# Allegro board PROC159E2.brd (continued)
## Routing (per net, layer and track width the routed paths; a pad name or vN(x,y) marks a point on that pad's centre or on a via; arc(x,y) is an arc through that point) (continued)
HSEC_MMC0_D1: length 104.8
  L08_SIG2 w0.091: v1(49.11,52.98) 49.6,52.49 51.45,52.49 53.6,54.63 65.11,54.63 66.27,53.47 67.27,53.47 68.03,52.71 70.05,52.71 71.08,51.68 75.63,51.68 78.21,49.1 78.21,40.54 79.82,38.93 79.82,33.07 80.78,32.1 80.78,30.79 83.76,27.82 83.76,26.1 83.9,25.97 84.23,25.97 84.36,25.84 84.36,25.65 84.23,25.51 83.9,25.51 83.76,25.38 83.76,25.19 83.9,25.06 84.23,25.06 84.36,24.92 84.36,24.73 84.23,24.6 83.9,24.6 83.76,24.47 83.76,24.28 83.9,24.14 84.23,24.14 84.36,24.01 84.36,23.82 84.23,23.68 83.9,23.68 83.76,23.55 83.76,23.36 83.9,23.23 84.23,23.23 84.36,23.09 84.36,22.9 84.23,22.77 83.9,22.77 83.76,22.64 83.76,22.45 83.9,22.31 84.23,22.31 84.36,22.18 84.36,21.99 84.23,21.86 83.9,21.86 83.76,21.72 83.76,21.53 83.9,21.4 84.23,21.4 84.36,21.26 84.36,21.08 84.23,20.94 83.9,20.94 83.76,20.81 83.76,20.41 87.89,16.29 88.24,16.29 88.37,16.42 88.37,16.79 88.51,16.92 88.69,16.92 88.83,16.79 88.83,16.42 88.96,16.29 89.15,16.29 89.29,16.42 89.29,16.79 89.42,16.92 89.61,16.92 89.74,16.79 89.74,16.42 89.88,16.29 92.4,16.29 100.05,8.64 101.41,8.64 104,6.05 106.76,6.05 v1(107.24,5.58)
  BOTTOM w0.147: RA3.2 49.35,52.69 49.11,52.94 v1(49.11,52.98) ; J15.166 106.44,4.78 v1(107.24,5.58)
HSEC_MMC0_D2: length 104.7
  TOP w0.147: J15.167 v1(107.24,4.56)
  L08_SIG2 w0.091: v1(107.24,4.56) 107.69,5.01 107.69,7.8 107.29,8.19 103.48,8.19 100.84,10.83 99.96,10.83 99.42,11.37 99.42,11.92 97.88,13.47 96.95,13.47 93.09,17.33 93.09,19.05 92.23,19.92 91.42,19.92 90.42,20.93 90.42,21.12 90.7,21.4 90.7,21.59 90.57,21.72 90.38,21.72 90.09,21.44 89.9,21.44 89.77,21.58 89.77,21.77 90.05,22.05 90.05,22.24 89.92,22.37 89.73,22.37 89.45,22.09 89.26,22.09 89.12,22.22 89.12,22.41 89.41,22.69 89.41,22.88 89.27,23.02 89.08,23.02 88.8,22.73 88.61,22.73 88.48,22.87 88.48,23.06 88.76,23.34 88.76,23.53 88.63,23.66 88.44,23.66 88.15,23.38 87.96,23.38 87.83,23.52 87.83,23.7 88.11,23.99 88.11,24.18 87.98,24.31 87.79,24.31 87.51,24.03 87.23,24.03 87.02,24.24 87.02,26.26 83.12,30.16 83.12,40.12 81.4,41.83 81.4,44.69 79.31,46.78 79.31,50.72 77.34,52.69 71.51,52.69 70.72,53.48 68.35,53.48 67.59,54.24 66.59,54.24 65.43,55.41 50.49,55.41 48.89,53.81 48.45,53.81 48.22,53.58 v1(48.22,52.98)
  BOTTOM w0.147: v1(48.22,52.98) 48.22,52.6 RA3.1
HSEC_MMC0_D3: length 104.7
  L08_SIG2 w0.091: v1(107.24,7.61) 106.93,7.92 103.36,7.92 101.77,9.51 100.34,9.51 99.15,10.71 99.15,11.77 97.73,13.19 96.84,13.19 92.82,17.21 92.82,18.84 92.18,19.48 90.07,19.48 89.71,19.84 89.71,20.03 89.94,20.27 89.94,20.46 89.81,20.59 89.62,20.59 89.38,20.35 89.19,20.35 89.06,20.49 89.06,20.68 89.3,20.91 89.3,21.1 89.16,21.24 88.97,21.24 88.74,21 88.55,21 88.41,21.13 88.41,21.32 88.65,21.56 88.65,21.75 88.52,21.88 88.33,21.88 88.09,21.65 87.9,21.65 87.77,21.78 87.77,21.97 88,22.21 88,22.4 87.87,22.53 87.68,22.53 87.44,22.29 87.25,22.29 86.56,22.98 86.56,26.31 82.67,30.2 82.67,40 81.09,41.59 81.09,44.5 79.03,46.55 79.03,50.61 77.22,52.42 71.4,52.42 70.53,53.29 68.27,53.29 67.51,54.05 66.51,54.05 65.35,55.21 50.74,55.21 48.68,53.15 48.68,52.84 48.4,52.55 47.76,52.55 v1(47.33,52.98)
  BOTTOM w0.147: v1(47.33,52.98) 47.33,52.5 RA5.4 ; J15.168 107.24,3.92 107.73,4.41 107.73,7.11 v1(107.24,7.61)
HSEC_MMC0_SDCD: length 102.5
  L08_SIG2 w0.091: v1(108.84,6.59) 108.32,7.11 108.32,8.1 107.54,8.88 105.38,8.88 104.79,9.48 103.37,9.48 100.73,12.11 100.07,12.11 98.47,13.7 98.47,13.89 97.6,14.76 96.44,14.76 93.74,17.46 93.74,20.5 84.58,29.66 84.58,31.93 83.93,32.59 83.93,40.38 82.01,42.29 82.01,45.02 79.86,47.17 79.86,50.95 77.56,53.24 71.6,53.24 70.97,53.87 68.56,53.87 67.8,54.63 66.75,54.63 65.59,55.79 48.37,55.79 v1(45.55,52.98)
  BOTTOM w0.147: J15.170 108.04,5.79 v1(108.84,6.59) ; v1(45.55,52.98) 45.55,52.94 45.8,52.69 RA5.2
HSEC_MMC0_WP: length 104.3
  TOP w0.147: v1(108.84,7.61) 108.04,6.81 J15.169
  L08_SIG2 w0.091: v1(108.84,7.61) 108.84,8.06 107.69,9.21 105.49,9.21 104.95,9.75 103.48,9.75 101.87,11.36 101.87,11.71 100.07,13.52 99.23,13.52 97.71,15.04 96.55,15.04 94.02,17.57 94.02,20.72 84.98,29.76 84.98,32.02 84.31,32.68 84.31,40.47 82.28,42.5 82.28,45.13 80.13,47.28 80.13,51.06 77.68,53.52 71.6,53.52 70.98,54.14 68.61,54.14 67.98,54.76 67.98,55.26 67.71,55.53 67.18,55.53 66.39,56.33 65.89,56.33 65.55,55.99 47.77,55.99 v1(45.59,53.8)
  BOTTOM w0.147: RA5.1 45.16,52.63 44.98,52.81 44.98,53.2 v1(45.59,53.8)
HSEC_SDFM0_CLK0: length 64.2
  TOP w0.147: U1.B16 v1(65.78,46.43)
  L08_SIG2 w0.091: v1(65.78,46.43) 65.37,46.02 64.02,46.02 63.79,45.79 63.79,42.27 64.04,42.02 67.69,42.02 68.67,41.04 69.34,41.04 70.13,40.25 70.13,34.22 69.45,33.54 69.45,27.41 67.64,25.6 67.64,23.36 66.6,22.32 66.6,18.71 65.82,17.92 62.81,17.92 59.35,14.46 59.35,13.26 56.97,10.87 55.19,10.87 49.89,5.58 v1(48.64,5.58)
  BOTTOM w0.147: J15.72 48.64,3.92 48.18,4.37 48.18,5.12 v1(48.64,5.58)
HSEC_SDFM0_CLK1: length 59.5
  TOP w0.147: R422.2 63.82,49.19 v1(65.78,47.23) U1.A16 ; v1(61.44,6.59) 60.64,5.79 J15.101
  L08_SIG2 w0.091: v1(65.78,47.23) 66.15,47.23 66.64,46.75 66.64,45.38 71.15,40.87 71.15,39.29 71.8,38.64 71.8,34.8 70.22,33.22 70.22,29.96 71.35,28.83 71.35,27.58 70.93,27.16 70.93,23.96 69.56,22.6 69.56,18.72 66.84,16 65.11,16 59.85,10.75 59.85,8.18 v1(61.44,6.59)
HSEC_SDFM0_CLK2: length 63.4
  TOP w0.147: U1.B15 v1(64.98,46.43) ; J15.105 62.24,5.71 v1(63.03,6.5)
  L08_SIG2 w0.091: v1(64.98,46.43) 65.23,46.43 65.62,46.82 65.97,46.82 66.36,46.43 66.36,45.3 70.86,40.8 70.86,34.13 70.03,33.3 70.03,26.95 68.37,25.3 68.37,23.75 69.31,22.81 69.31,18.75 67.23,16.66 63.79,16.66 58.56,11.43 58.56,7.49 59.14,6.91 59.14,6.53 59.64,6.04 59.98,6.04 60.63,5.38 60.63,4.76 61.26,4.13 61.62,4.13 62.61,5.12 62.61,6.07 v1(63.03,6.5)
HSEC_SDFM0_CLK3: length 57.5
  TOP w0.147: v1(63.72,10.39) 63.72,9.94 63.88,9.77 63.88,4.44 63.84,4.4 J15.109 ; U1.A15 v1(64.98,47.23)
  L08_SIG2 w0.091: v1(64.98,47.23) 64.98,47.6 65.2,47.82 67.38,47.82 68.1,47.1 68.1,44.61 71.64,41.07 71.64,39.5 72.25,38.89 72.25,34.65 71.5,33.91 71.5,32.87 71.25,32.62 71.25,32.04 71.97,31.31 71.97,26.93 73.43,25.47 73.43,23.78 72.25,22.6 72.25,18.8 71.5,18.05 69.43,18.05 63.98,12.6 63.98,10.65 v1(63.72,10.39)
HSEC_SDFM0_D0: length 53.6
  TOP w0.147: J15.91 v1(56.64,4.56) ; U1.D14 v1(64.18,44.83)
  L08_SIG2 w0.091: v1(56.64,4.56) 57.73,5.65 57.73,11.12 63.63,17.02 65.77,17.02 66.08,17.33 66.08,17.88 66.82,18.62 66.82,22.23 67.89,23.29 67.89,25.5 69.64,27.26 69.64,33.46 70.37,34.19 70.37,40.6 66.54,44.42 64.59,44.42 v1(64.18,44.83)
HSEC_SDFM0_D1: length 85.7
  TOP w0.147: J15.99 v1(59.84,4.56) ; U1.D13 v1(63.38,44.83)
  L08_SIG2 w0.091: v1(59.84,4.56) 60.81,3.58 62.93,3.58 63.65,4.31 63.65,6.72 66.72,9.78 66.93,10 66.93,12.29 69.22,14.58 74.45,14.58 78.59,18.71 78.59,20.28 79.04,20.72 79.04,24.92 80.95,26.83 80.95,28.49 78.21,31.23 78.21,37.23 76.43,39.02 76.43,42.76 75.95,43.23 75.95,44.06 73.27,46.75 73.27,48.62 72.32,49.57 69.71,49.57 68.69,50.59 68.46,50.59 68.29,50.76 68.29,51.25 68,51.54 67.52,51.54 66.75,52.31 65.45,52.31 v1(64.66,53.1)
  BOTTOM w0.114: 63.78,47.56 63.78,45.23 v1(63.38,44.83)
  BOTTOM w0.147: 63.78,47.56 63.78,48.42 64.66,49.31 v1(64.66,53.1) R421.2
HSEC_SDFM0_D2: length 69.1
  TOP w0.147: U1.C13 v1(63.38,45.63) ; J15.103 v1(61.44,4.56)
  L08_SIG2 w0.091: v1(63.38,45.63) 63.38,45.66 63.79,46.08 63.79,47.39 64.71,48.31 67.58,48.31 68.6,47.29 68.6,45.09 69.81,43.88 70.89,43.88 72.95,41.82 72.95,34.48 72.63,34.16 72.63,31.23 73.15,30.71 73.15,29.65 72.72,29.21 72.72,26.87 73.92,25.67 73.92,23.58 72.73,22.4 72.73,18.59 71.83,17.69 69.59,17.69 65.12,13.23 65.12,10.46 64.41,9.75 62.77,9.75 61.44,11.08 61.08,11.08 60.4,10.4 60.4,8.56 60.88,8.08 61.56,8.08 62.05,7.6 62.05,6.34 61.65,5.94 61.28,5.94 61.01,5.67 61.01,4.99 v1(61.44,4.56)
HSEC_SDFM0_D3: length 59.3
  TOP w0.147: J15.107 v1(63.04,4.56) ; U1.C14 v1(64.18,45.63)
  L08_SIG2 w0.091: v1(63.04,4.56) 62.43,3.95 61.19,3.95 60.45,4.69 60.45,5.31 59.9,5.85 59.56,5.85 58.79,6.62 58.79,6.88 58.38,7.29 58.38,11.51 63.71,16.84 67.15,16.84 69.07,18.76 69.07,22.71 68.13,23.65 68.13,25.4 69.83,27.11 69.83,33.38 70.62,34.16 70.62,40.7 66.1,45.22 64.59,45.22 v1(64.18,45.63)
HSEC_SPI0_CLK: length 78.5
  TOP w0.147: J15.71 v1(48.64,4.56) ; R150.1 v1(61.41,51.73) R139.1
  L08_SIG2 w0.091: v1(61.41,51.73) 61.41,48.1 60.06,46.75 60.06,40.63 60.83,39.86 67.59,39.86 67.98,39.46 67.98,32.26 67.4,31.67 67.4,26.74 66.67,26.01 66.67,23.66 65.7,22.69 65.7,19.08 65.44,18.83 62.44,18.83 58.45,14.83 58.45,13.39 56.84,11.78 49.76,11.78 45.01,7.04 45.01,4.38 45.39,4 48.08,4 v1(48.64,4.56)
HSEC_SPI0_CS0: length 63.5
  TOP w0.147: U1.C11 v1(61.78,45.63) ; J15.73 49.44,5.79 v1(50.24,6.59)
  L08_SIG2 w0.091: v1(61.78,45.63) 61.39,45.24 61.39,41.47 61.62,41.24 67.77,41.24 68.32,40.69 69.17,40.69 69.62,40.25 69.62,39.23 69.12,38.73 69.12,36.13 69.89,35.36 69.89,34.25 69.26,33.62 69.26,27.56 67.4,25.7 67.4,23.42 66.39,22.41 66.39,18.8 65.73,18.14 62.72,18.14 59.13,14.55 59.13,13.3 56.89,11.06 55.12,11.06 50.65,6.59 v1(50.24,6.59)
HSEC_SPI0_D0: length 70.3
  TOP w0.147: J15.67 v1(47.04,4.56) ; U1.C10 v1(60.98,45.63)
  L08_SIG2 w0.091: v1(47.04,4.56) 47.04,4.93 48.16,6.06 48.91,6.06 49.9,7.05 50.85,7.05 55.04,11.24 56.82,11.24 58.92,13.34 58.92,14.64 62.63,18.36 65.64,18.36 66.17,18.89 66.17,22.5 67.15,23.49 67.15,25.8 67.88,26.53 67.88,31.29 69.06,32.47 69.06,34.54 68.85,34.75 68.85,38.91 69.3,39.36 69.3,39.87 68.78,40.39 60.87,40.39 60.59,40.67 60.59,45.24 v1(60.98,45.63)
  BOTTOM w0.147: v1(60.98,45.63) 60.45,46.16 60.45,47.46 61.47,48.48 R151.1
HSEC_SPI0_D1: length 65.1
  TOP w0.147: J15.69 47.84,5.79 v1(48.64,6.59) ; U1.B11 v1(61.78,46.43)
  L08_SIG2 w0.091: v1(48.64,6.59) 48.96,6.91 48.96,7.19 53.19,11.42 56.74,11.42 58.67,13.35 58.67,14.74 62.53,18.61 65.53,18.61 65.92,18.99 65.92,22.6 66.91,23.59 66.91,25.91 67.64,26.64 67.64,31.45 68.19,32 68.19,39.65 67.72,40.12 60.86,40.12 60.35,40.63 60.35,45.64 60.73,46.02 61.37,46.02 v1(61.78,46.43)
HSEC_SPI1_CLK: length 17.1
  TOP w0.147: U8.3 v1(61.26,10.66) ; J15.79 v1(51.84,4.56)
  L03_SIG1 w0.091: v1(51.84,4.56) 52.6,4.56 53.16,5.11 57.44,5.11 59.46,7.13 60.07,7.13 61.68,8.75 61.68,10.24 v1(61.26,10.66)
HSEC_SPI1_CS0: length 19.9
  TOP w0.147: v1(53.44,6.59) 52.64,5.79 J15.81 ; v1(61.97,16.12) 61.91,16.18 U8.13
  L03_SIG1 w0.091: v1(53.44,6.59) 53.95,6.59 55.04,7.68 56.14,7.68 61.97,13.51 v1(61.97,16.12)
HSEC_SPI1_D0: length 22.4
  TOP w0.147: v1(64.04,13.72) 63.21,12.89 U8.6 ; J15.75 v1(50.24,4.56)
  L03_SIG1 w0.091: v1(64.04,13.72) 63.67,13.72 59.75,9.8 59.75,8.9 56.98,6.13 53.2,6.13 52.22,5.15 50.83,5.15 v1(50.24,4.56)
HSEC_SPI1_D1: length 23.8
  TOP w0.147: U8.10 v1(63.86,16.13) ; J15.77 51.04,5.79 v1(51.84,6.59)
  L03_SIG1 w0.091: v1(51.84,6.59) 52.83,6.59 53.42,7.18 54.05,7.18 54.99,8.11 56.14,8.11 61.16,13.13 61.16,15.91 61.79,16.54 63.45,16.54 v1(63.86,16.13)
HSEC_TCK: length 83.3
  TOP w0.147: v1(40.74,59.7) R183.2 40.18,60.34 39.75,60.78 39.75,61.96 39.32,62.39 U30.14 ; J15.5 v1(19.04,4.56)
  L03_SIG1 w0.091: v1(40.74,59.7) 39.78,59.7 37.96,61.52 31.56,61.52 25.12,55.08 22.85,55.08 22.26,54.49 22.26,34.15 24.73,31.68 24.73,23.83 24.72,23.82 19.5,18.6 19.5,10.28 19.73,10.05 19.73,5.25 v1(19.04,4.56)
HSEC_TDI: length 72.9
  TOP w0.147: v1(29.98,61.58) R181.2 30.54,60.83 30.8,61.09 U30.5
  L03_SIG1 w0.091: v1(19.04,7.61) 18.37,8.28 18.37,14.23 19.28,15.15 19.28,18.65 24.54,23.91 24.54,31.6 22.07,34.07 22.07,59.55 24.1,61.58 v1(29.98,61.58)
  BOTTOM w0.147: v1(19.04,7.61) 19.84,6.81 J15.8
HSEC_TDO: length 74.2
  TOP w0.147: U30.2 31.17,63.04 30.55,62.43 R180.2 v1(29.98,63.22)
  L03_SIG1 w0.091: v1(19.04,5.58) 17.98,6.63 17.98,14.36 18.92,15.3 18.92,18.8 22.16,22.04 22.16,23.9 23.88,25.61 23.88,31.75 21.71,33.92 21.71,59.77 24.44,62.5 27.44,62.5 28.17,63.22 v1(29.98,63.22)
  BOTTOM w0.147: J15.6 19.04,3.92 19.49,4.37 19.49,5.12 v1(19.04,5.58)
HSEC_TMS: length 90.2
  TOP w0.147: v1(40.64,58.28) 40.74,58.38 R182.2 39.97,58.95 39.62,59.3 39.62,59.93 39.11,60.44 U30.11 ; v1(19.05,6.59) 18.24,5.78 J15.3
  L03_SIG1 w0.091: v1(40.64,58.28) 41.39,59.04 41.39,60.32 40.62,61.1 38.64,61.1 37.91,61.83 31.69,61.83 31.3,62.23 29.33,62.23 29.1,62 24.26,62 21.89,59.63 21.89,34 24.36,31.53 24.36,23.98 19.1,18.72 19.1,15.22 18.17,14.29 18.17,7.47 v1(19.05,6.59)
HSEC_UART1_RXD: length 117.1
  L08_SIG2 w0.091: v1(25.65,17.51) 24.99,18.17 24.49,18.17 24.43,18.23 18.4,18.23 13.33,23.3 13.33,26.91 12.63,27.61 12.63,31.65 13.41,32.44 13.98,32.44 16.84,35.3 16.84,36.52 14.48,38.88 14.48,54.05 18.7,58.27 18.7,60.75 26.43,68.48 v1(27.61,68.48)
  BOTTOM w0.147: U44.3 v1(27.61,68.48) ; J15.76 50.24,3.86 50.74,4.37 50.74,6.63 54.53,10.41 54.53,10.84 55.09,11.4 55.09,14.27 53.77,15.59 53.77,16.26 53.18,16.86 49.86,16.86 47.4,19.32 27.45,19.32 v1(25.65,17.51)
HSEC_UART1_TXD: length 126.6
  L08_SIG2 w0.091: v1(24.76,17.51) 24.22,18.05 17.18,18.05 13.15,22.08 13.15,25.21 10.27,28.09 10.27,31.58 11.31,32.62 13.9,32.62 16.66,35.38 16.66,36.36 14.17,38.85 14.17,58.59 26.02,70.43 v1(30.22,70.43)
  BOTTOM w0.147: v1(24.76,17.51) 26.86,19.61 47.28,19.61 47.52,19.61 49.98,17.15 53.3,17.15 54.07,16.39 54.07,15.71 55.38,14.4 55.38,11.28 54.83,10.72 54.83,10.29 51.04,6.5 J15.78 ; U44.6 v1(30.22,70.43)
HSEC_VREF_3V3: length 5.5
  TOP w0.381: J15.45 35.04,4.24 34.3,4.97 R417.1
I2C0_MUX_OE#: length 2.3
  BOTTOM w0.147: R165.1 40.37,71.56 U26.15
I2C0_MUX_SEL: length 17.1
  TOP w0.147: v1(49.04,73.03) 49.85,72.22 52.7,72.22 54.04,70.88 54.04,69.19 55.07,68.16 56.51,68.16 57.46,67.21 v1(57.46,66.54)
  BOTTOM w0.147: U26.1 48.69,72.21 48.73,72.25 R164.1 ; R164.1 R162.2 ; R164.1 v1(49.04,73.03) ; U60.10 v1(57.46,66.54)
I2C0_SCL: length 109.8
  TOP w0.147: v1(70.99,95.24) 71.44,95.24 71.65,95.44 J8.40
  L03_SIG1 w0.091: v1(70.99,95.24) 70.56,94.81 68.12,94.81 66.97,95.95 50.54,95.95 47.49,92.91 47.49,75.81 46.04,74.36 v1(46.04,71.56)
  L08_SIG2 w0.091: v1(110.06,91.12) 107.05,94.12 107.05,101.88 100.81,108.12 86.76,108.12 84.91,106.28 82.08,106.28 81.62,105.81 78.9,105.81 75.15,102.06 75.15,100.2 70.99,96.03 v1(70.99,95.24)
  BOTTOM w0.147: R154.2 v1(70.99,95.24) ; U28.6 v1(110.06,91.12) ; U26.2 v1(46.04,71.56)
I2C0_SDA: length 114.5
  TOP w0.147: J8.42 70.83,95.84 v1(70.23,95.24)
  L03_SIG1 w0.091: v1(46.04,69.61) 45.54,70.11 45.54,74.21 47.2,75.87 47.2,93.01 50.41,96.21 67.05,96.21 68.02,95.24 v1(70.23,95.24)
  L08_SIG2 w0.091: v1(108.79,91.12) 106.78,93.13 106.78,101.77 100.63,107.92 86.98,107.92 85.05,105.99 82.74,105.99 81.57,104.83 78.22,104.83 75.37,101.97 75.37,100.11 71.69,96.42 71.69,95.23 71.19,94.73 70.73,94.73 v1(70.23,95.24)
  BOTTOM w0.147: R155.2 70.97,96.43 70.23,95.69 v1(70.23,95.24) ; U28.5 v1(108.79,91.12) ; U26.5 v1(46.04,69.61)
ICSSM0_MUX_SEL: length 121.7
  TOP w0.147: U87.10 78.76,60.89 v1(79.01,60.64) 78.76,60.39 U87.9 ; R1383.2 SW14.1 47.31,84.21 48.04,84.94 51.18,84.94 52.45,83.67 54.51,83.67 v1(59.63,78.54)
  L03_SIG1 w0.091: v1(59.63,78.54) 59.06,78.54 58.65,78.12 58.65,74.01 59.96,72.7 60.52,72.7 60.89,72.33 69.4,72.33 71.34,74.27 v1(72.66,74.27)
  BOTTOM w0.147: U60.21 53.11,70.24 52.93,70.42 52.93,71.06 51.24,72.75 51.24,76.18 51.84,76.79 56.5,76.79 58.26,78.54 v1(59.63,78.54) 61.37,78.54 63.08,80.25 63.08,81.58 61.94,82.72 61.94,87.9 60.7,89.13 60.7,90.18 61.53,91.01 61.53,91.48 62,91.95 62,92.38 61.83,92.55 61.83,93.5 66.77,98.45 66.77,101.59 68.17,102.99 70.96,102.99 71.84,102.12 75.52,102.12 76.92,103.51 79.16,103.51 81.04,101.63 81.21,101.63 81.49,101.63 81.7,101.84 U88.9 ; v1(72.66,74.27) 73.31,73.61 73.31,66.74 73.92,66.13 73.92,63.53 75.37,62.09 77.57,62.09 v1(79.01,60.64)
ICSSM1_ETH_LED2: length 8.1
  BOTTOM w0.147: J7.12 107.62,79.43 106.25,79.43 105.73,79.95 Q6.3
ICSSM1_INTN: length 93.5
  TOP w0.147: R195.2 48.31,47.42 47.63,46.73 v1(47.63,46.27)
  L08_SIG2 w0.091: v1(47.63,46.27) 47.36,46.54 45.06,46.54 43.73,47.88 43.73,51.48 44.3,52.05 44.3,56.7 45.12,57.52 45.12,61.03 46.73,62.63 49.44,62.63 50.67,61.41 50.67,60.31 53.86,57.12 64.08,57.12 64.85,57.89 65.37,57.89 67.34,55.92 68.85,55.92 69.21,55.56 69.65,55.56 69.94,55.27 69.94,54.86 70.14,54.67 71.17,54.67 71.76,54.09 81.52,54.09 82.98,55.55 86.64,55.55 91.99,60.9 91.99,61.63 89.94,63.68 v1(89.94,73.01)
  BOTTOM w0.147: R214.2 90.07,74.77 90.4,74.44 90.4,73.47 v1(89.94,73.01) 89.95,72.99 89.95,72.12 U35.44
ICSSM1_LED_GREEN: length 7
  TOP w0.147: J7.13 107.82,60.85 R218.2 Q7.3
ICSSM1_LED_YELLOW: length 8.9
  BOTTOM w0.147: Q8.3 108.54,57.55 108.54,57.55 R219.2 107.82,58.1 107.82,58.11 107.82,59.17 108.71,60.06 110.74,60.06 111.3,60.62 J7.14
ICSSM1_MUX_EN1: length 2.7
  TOP w0.147: U87.8 v1(79.93,59.89)
  BOTTOM w0.147: v1(79.93,59.89) 79.97,59.85 R1381.1
ICSSM1_MUX_EN2: length 2.3
  BOTTOM w0.147: U88.8 80.52,101.34 80.21,101.65 R3861.2
ICSSM1_MUX_EN3: length 1.8
  BOTTOM w0.147: R3864.1 81.05,88.35 U89.8
ICSSM1_MUX_SEL: length 81
  TOP w0.147: v1(81.32,88.97) 80.85,89.44 80.85,101.63 v1(81.3,102.09) ; SW16.1 50.8,82.42 51.4,81.82 R3873.2 55.78,81.82 58.11,79.49 58.11,78.71 v1(59.13,77.69)
  L03_SIG1 w0.091: v1(72.66,76.22) 70.7,74.27 61.82,74.27 61.46,73.91 60.14,73.91 59.8,74.24 59.8,77.02 v1(59.13,77.69)
  L08_SIG2 w0.091: v1(72.66,76.22) 75.7,76.22 76.31,75.61 76.31,74.41 78.43,72.28 78.82,72.28 80.19,73.66 80.19,78.12 81.99,79.92 81.99,84.44 82.37,84.82 82.37,87.92 v1(81.32,88.97)
  BOTTOM w0.147: v1(59.13,77.69) 59.97,76.85 59.97,74.02 60.12,73.87 60.31,73.87 60.74,73.44 60.74,72.03 59.46,70.74 U60.3 ; U88.10 81.55,102.34 v1(81.3,102.09) ; U89.9 81.44,88.85 v1(81.32,88.97) 81.69,89.35 U89.10
ICSSM1_RESETN: length 40
  TOP w0.147: U36.4 R220.2 81.71,43.91 79.49,46.14 79.49,50.35 83.77,54.63 83.77,59.26 87.82,63.31 87.82,64.36 89.79,66.32 89.79,70.09 89.27,70.6 89.27,73.12 v1(89.94,73.78)
  BOTTOM w0.147: v1(89.94,73.78) 89.42,73.27 U35.43
ICSSM2_MUX_EN1: length 1.8
  BOTTOM w0.147: U82.8 R3843.1
ICSSM2_MUX_EN2: length 1.6
  TOP w0.147: U85.8 R3852.1
ICSSM2_MUX_EN3: length 1.6
  TOP w0.147: U84.8 R3849.1
ICSSM2_MUX_SEL: length 117.1
  TOP w0.147: U84.9 93.89,88.85 94.14,89.1 ; v1(96.37,90.27) 95.2,89.1 94.14,89.1 ; U85.10 93.89,102.34 v1(94.14,102.09) 93.89,101.84 U85.9 ; v1(66.18,60.64) 65.32,60.64 64.24,61.72 SW15.1 R3844.2 62.34,63.3 61.82,62.78 61.19,62.78 60.02,63.95 60.02,66.17 60.65,66.79 60.65,68.07 60.15,68.57 60.15,69.85 59.14,70.87 59.14,73.07 v1(60.44,74.36) ; U84.10 93.89,89.35 94.14,89.1
  L03_SIG1 w0.091: v1(94.14,102.09) 92.6,103.62 90.38,103.62 90.14,103.86 90.14,104.33 89.58,104.9 88.78,104.9 88.58,105.1 88.58,105.53 87.26,106.84 85.8,106.84 85.62,106.66 84.73,106.66 84.55,106.84 84.55,107.38 84.31,107.63 81.63,107.63 78.05,104.05 78.05,102.87 75.11,99.92 75.11,87.81 73.98,86.68 73.85,86.68 73.83,86.69 72.86,86.69 71.85,85.68 71.85,85.06 69.92,83.14 69.92,82.64 69.52,82.24 65.48,82.24 62.45,79.2 62.45,76.38 v1(60.44,74.36)
  BOTTOM w0.147: v1(94.14,102.09) 95.36,100.86 100.06,100.86 101.13,99.8 101.13,92.05 100.35,91.28 97.37,91.28 v1(96.37,90.27) ; U82.9 66.43,60.39 v1(66.18,60.64) 66.43,60.89 U82.10 ; v1(60.44,74.36) 61.2,73.6 61.2,71.76 59.69,70.24 U60.4
ICSSM2_PWDN/INTN: length 85.8
  TOP w0.147: v1(70.34,90.9) R267.1 70.89,90.14 71.59,89.44 J8.10
  L08_SIG2 w0.091: v1(70.34,90.9) 70.34,90.06 70.92,89.47 70.92,88.44 67.81,85.33 67.3,85.33 66.44,84.47 66.44,82.47 67.03,81.88 67.03,78.74 66.63,78.34 66.63,77.18 65.62,76.17 65.62,64.43 63.61,62.42 61,62.42 60.51,62.91 59.4,62.91 56.89,60.4 53.33,60.4 50.22,63.51 49.34,63.51 49.15,63.33 43.13,63.33 41.8,62 41.8,58.6 43.34,57.07 43.34,55.58 43.93,54.99 43.93,52.23 42.65,50.95 42.65,48.5 44.91,46.23 45.98,46.23 47.35,44.86 47.35,43.22 v1(48.51,42.07)
  BOTTOM w0.147: R191.2 v1(48.51,42.07)
ICSSM2_RESETN: length 24.1
  TOP w0.147: v1(76.53,100.44) 75.42,99.33 68.76,99.33 67.99,98.56 67.99,94.87 68.54,94.32 68.54,92.01 69.18,91.38 70.72,91.38 71.04,91.06 71.04,90.51 71.71,89.84 J8.12
  BOTTOM w0.147: v1(76.53,100.44) 76.99,100.44 77.26,100.71 R266.2 U39.4
ICSSM_BRD_CONN_DET: length 2.4
  TOP w0.147: R263.1 70.99,93.71 71.92,94.64 J8.36
ICSSM_INH: length 2
  TOP w0.147: J8.26 71.92,92.64 71.8,92.77 71.13,92.77 71.04,92.68 R264.2
ICSSM_MII0/MII1_COL_ADD: length 11
  TOP w0.147: J8.14 73.03,90.24 73.09,90.3 73.84,90.3 v1(74.28,89.86) ; R509.2 v1(72.05,84.11)
  BOTTOM w0.147: v1(74.28,89.86) 74.8,89.33 74.8,85.79 73.77,84.76 72.69,84.76 v1(72.05,84.11) R509.2
ICSSM_MII0/MII1_COL_ON: length 2.2
  TOP w0.147: R493.2 v1(99.76,96.93) TP83.1
  BOTTOM w0.147: R493.2 v1(99.76,96.93)
ICSSM_MII0/MII1_CRS_ADD: length 12.8
  TOP w0.147: J8.30 v1(71.53,93.44) ; R510.2 70.43,84.66 70.57,84.8 v1(70.88,84.8)
  BOTTOM w0.147: R510.2 70.43,84.66 70.57,84.8 v1(70.88,84.8) 72.56,86.48 72.56,92.42 v1(71.53,93.44)
ICSSM_MII0/MII1_CRS_ON: length 2.2
  TOP w0.147: R494.2 v1(99.76,97.92) TP84.1
  BOTTOM w0.147: R494.2 v1(99.76,97.92)
ICSSM_MII0/MII1_RXCLK_ADD: length 35.1
  TOP w0.147: R531.2 v1(75.44,67.69) ; J8.19 v1(75.93,91.44)
  BOTTOM w0.147: v1(75.93,91.44) 76.38,91.9 76.38,92.82 76.58,93.02 76.97,93.02 77.48,93.52 77.75,93.52 78.05,93.22 78.05,92.87 75.8,90.62 75.8,84.43 77.59,82.64 77.59,80.13 74.29,76.83 74.29,68.84 v1(75.44,67.69) R531.2
ICSSM_MII0/MII1_RXCLK_ON: length 64.4
  TOP w0.147: R483.2 v1(99.89,92.95)
  L08_SIG2 w0.091: v1(81.94,69.79) 82.51,70.36 83.34,70.36 83.69,70 83.69,68.09 84.04,67.75 84.97,67.75 86,68.77 86,74.4 87.48,75.88 87.48,77.46 90.41,80.4 96.32,80.4 99.66,83.74 99.66,87.06 100.63,88.03 100.63,88.95 100.65,88.95 101.56,89.87 101.56,97.85 101.39,98.03 101.07,98.03 100.9,97.86 100.9,97.5 100.79,97.39 100.51,97.39 100.4,97.28 100.4,97.13 100.51,97.02 100.79,97.02 100.9,96.92 100.9,96.77 100.79,96.66 100.51,96.66 100.4,96.55 100.4,96.4 100.51,96.29 100.79,96.29 100.9,96.19 100.9,96.03 100.79,95.93 100.51,95.93 100.4,95.82 100.4,95.67 100.51,95.56 100.79,95.56 100.9,95.45 100.9,95.3 100.79,95.2 100.51,95.2 100.4,95.09 100.4,94.94 100.51,94.83 100.79,94.83 100.9,94.72 100.9,94.57 100.79,94.46 100.51,94.46 100.4,94.36 100.4,94.21 100.51,94.1 100.79,94.1 100.9,93.99 100.9,90.11 100.75,89.96 100.44,89.96 100.32,90.08 100.32,92.52 v1(99.89,92.95)
  BOTTOM w0.147: R483.2 v1(99.89,92.95) ; v1(81.94,69.79) 82.12,69.96 R212.1
ICSSM_MII0/MII1_RXD0_ADD: length 35.1
  TOP w0.147: R533.2 v1(78.21,73.64) ; v1(76.84,92.52) 76.35,92.02 75.76,92.02 75.54,92.24 J8.23
  L08_SIG2 w0.091: v1(76.84,92.52) 77.66,91.69 77.66,91.27 77.55,91.16 76.57,91.16 76.47,91.06 76.47,90.91 76.57,90.8 77.55,90.8 77.66,90.69 77.66,90.54 77.55,90.43 76.57,90.43 76.47,90.33 76.47,90.17 76.57,90.07 77.55,90.07 77.66,89.96 77.66,89.81 77.55,89.7 76.57,89.7 76.47,89.59 76.47,89.44 76.57,89.34 77.55,89.34 77.66,89.23 77.66,89.08 77.55,88.97 76.57,88.97 76.47,88.86 76.47,88.71 76.57,88.6 77.55,88.6 77.66,88.5 77.66,88.35 77.55,88.24 76.57,88.24 76.47,88.13 76.47,87.98 76.57,87.87 77.55,87.87 77.66,87.77 77.66,80.33 75.76,78.42 75.76,76.98 76.82,75.92 76.82,74.68 77.38,74.11 77.64,74.11 77.95,73.8 78.04,73.8 v1(78.21,73.64)
  BOTTOM w0.147: R525.2 77.6,73.64 v1(78.21,73.64)
ICSSM_MII0/MII1_RXD0_ON: length 66.6
  TOP w0.147: R237.1 85.48,69.84 v1(84.58,69.84) 83.87,69.84 R225.2 ; R476.2 v1(82.53,82.11)
  L03_SIG1 w0.091: v1(84.58,69.84) 83.07,68.33 80.61,68.33 80.27,68.67 80.27,70.54 78.72,72.1 78.01,72.1 77.71,71.8 77.71,71.17 76.69,70.15 75.25,70.15 74.78,69.67 74.63,69.67 74.14,70.15 73.99,70.15 73.89,70.04 73.89,69.89 74.37,69.41 74.37,69.26 74.26,69.15 74.11,69.15 73.63,69.63 73.47,69.63 73.37,69.53 73.37,69.38 73.85,68.89 73.85,68.74 73.74,68.63 73.59,68.63 73.11,69.12 72.96,69.12 72.85,69.01 72.85,68.86 73.33,68.38 73.33,68.22 73.23,68.12 73.07,68.12 72.59,68.6 72.44,68.6 72.33,68.49 72.33,68.34 72.81,67.86 72.81,67.71 71.77,66.66 71.62,66.66 71.35,66.93 71.2,66.93 71.09,66.82 71.09,66.67 71.36,66.41 71.36,66.25 71.25,66.15 71.1,66.15 70.84,66.41 70.68,66.41 70.58,66.31 70.58,66.16 70.84,65.89 70.84,65.74 70.74,65.63 70.59,65.63 70.32,65.9 70.17,65.9 70.06,65.79 70.06,65.64 70.33,65.37 70.33,65.22 70.22,65.11 70.07,65.11 69.8,65.38 69.65,65.38 69.54,65.27 69.54,65.12 69.81,64.85 69.81,64.7 69.48,64.38 69.15,64.38 68.8,64.73 68.8,65.16 71.15,67.51 71.15,67.93 74.38,71.16 75.57,71.16 75.79,71.38 75.79,72.86 76.13,73.21 76.7,73.21 76.8,73.1 76.8,71.4 76.91,71.29 77.06,71.29 77.17,71.4 77.17,73.1 77.28,73.21 78.38,73.21 79.77,74.6 79.77,81.71 80.17,82.11 v1(82.53,82.11)
  BOTTOM w0.147: U35.33 v1(84.58,69.84) ; R476.2 v1(82.53,82.11)
ICSSM_MII0/MII1_RXD1_ADD: length 35.3
  TOP w0.147: v1(78.63,72.72) 78.5,72.72 78.42,72.64 R534.2 ; v1(75.93,92.52) 75.8,92.64 J8.25
  L08_SIG2 w0.091: v1(78.63,72.72) 78.44,72.72 76.59,74.57 76.59,75.75 75.5,76.84 75.5,78.49 77.36,80.35 77.36,87.21 77.15,87.42 75,87.42 74.89,87.53 74.89,87.77 75,87.88 75.81,87.88 75.92,87.99 75.92,88.14 75.81,88.25 75,88.25 74.89,88.35 74.89,88.5 75,88.61 75.81,88.61 75.92,88.72 75.92,88.87 75.81,88.98 75,88.98 74.89,89.08 74.89,89.24 75,89.34 75.81,89.34 75.92,89.45 75.92,89.6 75.81,89.71 75,89.71 74.89,89.82 74.89,89.97 75,90.07 75.81,90.07 75.92,90.18 75.92,90.33 75.81,90.44 75,90.44 74.89,90.55 74.89,92.17 75.24,92.52 v1(75.93,92.52)
  BOTTOM w0.147: R534.2 78.42,72.64 78.5,72.72 v1(78.63,72.72)
ICSSM_MII0/MII1_RXD1_ON: length 66.8
  TOP w0.147: R477.2 83.11,80.57 v1(83.02,80.48) ; R238.1 84.7,70.98 v1(84.58,70.85) 84.45,70.98 R226.2
  L03_SIG1 w0.091: v1(83.02,80.48) 83.72,80.48 84.02,80.78 84.02,81.51 83.42,82.12 83.22,82.12 82.79,81.68 80.19,81.68 80.05,81.54 80.05,81.24 80.13,81.16 81.27,81.16 81.35,81.08 81.35,80.97 81.27,80.89 80.13,80.89 80.05,80.81 80.05,80.69 80.13,80.61 81.27,80.61 81.35,80.53 81.35,80.42 81.27,80.34 80.13,80.34 80.05,80.26 80.05,80.14 80.13,80.06 81.27,80.06 81.35,79.98 81.35,79.87 81.27,79.79 80.13,79.79 80.05,79.71 80.05,79.6 80.13,79.52 81.27,79.52 81.35,79.43 81.35,79.32 81.27,79.24 80.13,79.24 80.05,79.16 80.05,79.05 80.13,78.97 81.27,78.97 81.35,78.89 81.35,78.77 81.27,78.69 80.13,78.69 80.05,78.61 80.05,78.5 80.13,78.42 81.27,78.42 81.35,78.34 81.35,78.22 81.27,78.14 80.13,78.14 80.05,78.06 80.05,77.95 80.13,77.87 81.27,77.87 81.35,77.79 81.35,77.68 81.27,77.6 80.13,77.6 80.05,77.51 80.05,77.4 80.13,77.32 81.27,77.32 81.35,77.24 81.35,77.13 81.27,77.05 80.13,77.05 80.05,76.97 80.05,76.85 80.13,76.77 81.27,76.77 81.35,76.69 81.35,76.58 81.27,76.5 80.13,76.5 80.05,76.42 80.05,76.3 80.13,76.22 81.27,76.22 81.35,76.14 81.35,76.03 81.27,75.95 80.13,75.95 80.05,75.87 80.05,75.76 80.13,75.67 81.27,75.67 81.35,75.59 81.35,75.48 81.27,75.4 80.13,75.4 80.05,75.32 80.05,75.21 80.13,75.13 81.27,75.13 81.35,75.05 81.35,74.93 81.27,74.85 80.13,74.85 80.05,74.77 80.05,74.66 80.13,74.58 81.27,74.58 81.35,74.5 81.35,74.38 81.27,74.3 80.13,74.3 80.05,74.22 80.05,73.97 80.16,73.87 80.6,73.87 80.7,73.77 80.7,73.61 80.59,73.5 79.29,73.5 79.16,73.38 79.16,73.23 79.26,73.13 80.48,73.13 80.59,73.03 80.59,72.88 80.48,72.77 79.29,72.77 79.16,72.64 79.16,72.49 79.26,72.4 80.48,72.4 80.59,72.3 80.59,72.14 80.48,72.04 79.74,72.04 79.65,71.94 79.65,71.55 80.55,70.66 80.55,69.06 80.86,68.75 81.27,68.75 81.81,69.3 83.41,69.3 84.58,70.46 v1(84.58,70.85)
  BOTTOM w0.147: R477.2 83.11,80.57 v1(83.02,80.48) ; v1(84.58,70.85) 84.58,70.73 84.96,70.34 U35.34
ICSSM_MII0/MII1_RXD2_ADD: length 35
  TOP w0.147: R535.2 78.2,71.65 v1(78.2,71.66) 78.37,71.66 79.08,72.37 79.08,73.69 78.95,73.82 78.7,73.82 78.57,73.95 78.57,74.13 78.7,74.26 78.95,74.26 79.08,74.39 79.08,74.76 78.95,74.89 78.76,74.89 78.63,75.02 78.63,75.2 78.76,75.33 78.95,75.33 79.08,75.46 79.08,75.86 78.95,75.99 78.76,75.99 78.63,76.12 78.63,76.3 78.76,76.43 78.95,76.43 79.08,76.56 79.08,76.79 78.95,76.92 78.74,76.92 78.61,77.05 78.61,77.23 78.74,77.36 78.95,77.36 79.08,77.49 79.08,78.34 78.64,78.78 78.64,83.14 77.94,83.84 77.94,84.03 78.07,84.16 78.07,84.34 77.94,84.47 77.76,84.47 77.63,84.34 77.45,84.34 77.2,84.59 77.2,85 77.33,85.13 77.44,85.13 77.57,85.26 77.57,85.45 77.44,85.57 77.33,85.57 77.2,85.7 77.2,85.89 77.33,86.02 77.44,86.02 77.57,86.15 77.57,86.33 77.44,86.46 77.33,86.46 77.2,86.59 77.2,86.77 77.33,86.9 77.44,86.9 77.57,87.03 77.57,87.21 77.44,87.34 77.33,87.34 77.2,87.47 77.2,87.66 77.33,87.78 77.44,87.78 77.57,87.91 77.57,88.1 77.44,88.23 77.33,88.23 77.2,88.36 77.2,88.54 77.33,88.67 77.44,88.67 77.57,88.8 77.57,88.98 77.44,89.11 77.33,89.11 77.2,89.24 77.2,89.42 77.33,89.55 77.44,89.55 77.57,89.68 77.57,89.87 77.44,89.99 77.33,89.99 77.2,90.12 77.2,91.03 76.68,91.54 76.68,91.79 76.86,91.96 77.13,91.96 77.31,92.13 77.31,92.73 77.3,92.73 76.81,93.22 76.81,93.5 76.98,93.67 77.31,93.67 77.42,93.78 77.42,93.99 77.3,94.11 76.6,94.11 76.4,93.91 76.4,93.29 76.15,93.04 J8.27
  BOTTOM w0.147: R535.2 78.2,71.65 v1(78.2,71.66)
ICSSM_MII0/MII1_RXD2_ON: length 67.2
  TOP w0.147: R479.2 83.44,79.43 83.22,79.21 v1(83.22,78.55) ; R243.2 84.83,72.12 v1(84.58,71.87) 84.32,72.13 R231.1
  L03_SIG1 w0.091: v1(83.22,78.55) 83.84,78.55 84.04,78.74 84.04,79.94 83.82,80.15 83.4,80.15 83.16,79.91 82.76,79.91 82.6,80.08 82.6,80.66 82.85,80.91 83.69,80.91 83.75,80.96 83.75,81.4 83.41,81.74 83.25,81.74 82.91,81.41 81.83,81.41 81.63,81.2 81.63,80.92 81.71,80.84 82.12,80.84 82.2,80.76 82.2,80.65 82.12,80.57 81.71,80.57 81.63,80.49 81.63,80.38 81.71,80.3 82.12,80.3 82.2,80.22 82.2,80.1 82.12,80.02 81.71,80.02 81.63,79.94 81.63,79.83 81.71,79.75 82.12,79.75 82.2,79.67 82.2,79.55 82.12,79.47 81.71,79.47 81.63,79.39 81.63,79.28 81.71,79.2 82.12,79.2 82.2,79.12 82.2,79 82.12,78.92 81.71,78.92 81.63,78.84 81.63,78.73 81.71,78.65 82.12,78.65 82.2,78.57 82.2,78.46 82.12,78.38 81.71,78.38 81.63,78.3 81.63,78.18 81.71,78.1 82.12,78.1 82.2,78.02 82.2,77.91 82.12,77.83 81.71,77.83 81.63,77.75 81.63,77.63 81.71,77.55 82.12,77.55 82.2,77.47 82.2,77.36 82.12,77.28 81.71,77.28 81.63,77.2 81.63,77.08 81.71,77 82.12,77 82.2,76.92 82.2,76.81 82.12,76.73 81.71,76.73 81.63,76.65 81.63,76.54 81.71,76.46 82.12,76.46 82.2,76.38 82.2,76.26 82.12,76.18 81.71,76.18 81.63,76.1 81.63,75.99 81.71,75.91 82.12,75.91 82.2,75.83 82.2,75.71 82.12,75.63 81.71,75.63 81.63,75.55 81.63,75.44 81.71,75.36 82.12,75.36 82.2,75.28 82.2,75.16 82.12,75.08 81.71,75.08 81.63,75 81.63,74.89 81.71,74.81 82.12,74.81 82.2,74.73 82.2,74.62 82.12,74.54 81.71,74.54 81.63,74.45 81.63,74.11 81.47,73.96 81.18,73.96 81.01,73.78 81.01,73.17 81.16,73.01 82.8,73.01 82.89,72.93 82.89,72.81 82.8,72.73 80.98,72.73 80.9,72.65 80.9,72.54 80.98,72.46 82.8,72.46 82.89,72.38 82.89,72.27 82.8,72.19 80.98,72.19 80.9,72.11 80.9,71.99 80.98,71.91 82.8,71.91 82.89,71.83 82.89,71.72 82.8,71.64 80.98,71.64 80.9,71.56 80.9,71.44 80.98,71.36 82.8,71.36 82.89,71.28 82.89,71.17 82.8,71.09 80.98,71.09 80.9,71.01 80.9,70.89 80.98,70.81 82.8,70.81 82.89,70.73 82.89,70.62 82.8,70.54 80.98,70.54 80.9,70.46 80.9,69.25 81.02,69.12 81.25,69.12 81.42,69.29 81.42,70.04 81.63,70.25 82.3,70.25 82.38,70.17 82.38,69.72 82.46,69.64 82.58,69.64 82.66,69.72 82.66,70.17 82.74,70.25 83.89,70.25 84.05,70.41 84.05,70.57 83.97,70.65 83.31,70.65 83.23,70.73 83.23,70.85 83.31,70.93 83.97,70.93 84.05,71.01 84.05,71.12 83.97,71.2 83.31,71.2 83.23,71.28 83.23,71.4 83.31,71.48 84.18,71.48 v1(84.58,71.87)
  BOTTOM w0.147: U35.35 85.22,70.84 84.96,71.1 84.96,71.48 v1(84.58,71.87) ; R479.2 83.79,79.11 v1(83.22,78.55)
ICSSM_MII0/MII1_RXD3_ADD: length 35.4
  TOP w0.147: R536.2 77.6,70.67 v1(78.69,70.67) 78.69,71.47 79.43,72.22 79.43,78.48 78.99,78.92 78.99,83.56 78.84,83.71 78.69,83.71 78.56,83.84 78.56,84.03 78.69,84.16 78.84,84.16 78.99,84.31 78.99,84.52 78.64,84.87 78.46,84.87 78.35,84.76 78.16,84.76 78.03,84.89 78.03,85.08 78.14,85.19 78.14,85.37 77.92,85.59 77.92,90.22 77.79,90.35 77.67,90.35 77.54,90.48 77.54,90.66 77.67,90.79 77.79,90.79 77.92,90.92 77.92,91.1 77.79,91.23 77.67,91.23 77.54,91.36 77.54,91.54 77.67,91.67 77.79,91.67 77.92,91.8 77.92,92.87 77.79,93 77.67,93 77.54,93.13 77.54,93.31 77.67,93.44 77.79,93.44 77.92,93.57 77.92,94.17 77.6,94.49 77.6,95.54 77.45,95.68 77.24,95.68 77.07,95.51 76.73,95.51 76.6,95.38 76.6,95.2 76.73,95.07 76.89,95.07 77.03,94.92 77.03,94.64 76.85,94.46 76.35,94.46 75.98,94.08 75.98,93.62 75.8,93.44 J8.29
  BOTTOM w0.147: v1(78.69,70.67) 77.6,70.67 R536.2
ICSSM_MII0/MII1_RXD3_ON: length 66.8
  TOP w0.147: v1(83.83,77.57) 84.07,77.81 R480.2 ; R232.1 84.07,73.27 v1(84.58,72.76) 85.09,73.27 R244.2
  L03_SIG1 w0.091: v1(84.58,72.76) 84.18,72.76 83.92,73.01 83.92,73.65 84.26,73.98 84.92,73.98 85.01,74.08 85.01,74.76 85.11,74.86 85.24,74.86 85.34,74.76 85.34,74.08 85.44,73.98 85.78,73.98 86.25,73.52 86.25,73.16 86.17,73.08 85.51,73.08 85.43,73 85.43,72.89 85.51,72.81 86.17,72.81 86.25,72.73 86.25,72.61 86.17,72.53 85.51,72.53 85.43,72.45 85.43,72.34 85.51,72.26 86.17,72.26 86.25,72.18 86.25,72.06 86.17,71.98 85.51,71.98 85.43,71.9 85.43,71.79 85.51,71.71 86.17,71.71 86.25,71.63 86.25,71.28 85.81,70.85 85.81,70.62 85.73,70.54 85.43,70.54 85.35,70.46 85.35,70.34 85.43,70.26 85.73,70.26 85.81,70.18 85.81,70.07 85.73,69.99 85.43,69.99 85.35,69.91 85.35,69.8 85.43,69.72 85.73,69.72 85.81,69.64 85.81,69.52 85.73,69.44 85.43,69.44 85.35,69.36 85.35,69.25 85.43,69.17 85.73,69.17 85.81,69.09 85.81,68.87 85.55,68.6 85.2,68.6 85.05,68.75 85.05,72.04 84.79,72.3 84.4,72.3 84.15,72.05 84.15,71.91 84,71.75 83.28,71.75 83.17,71.85 83.17,73.03 82.96,73.25 82.95,73.25 82.92,73.28 82.01,73.28 81.91,73.37 81.91,74.13 82.05,74.26 82.35,74.26 82.49,74.39 82.49,74.61 82.57,74.69 82.88,74.69 82.96,74.61 82.96,73.94 83.04,73.86 83.16,73.86 83.24,73.94 83.24,74.61 83.32,74.69 83.43,74.69 83.51,74.61 83.51,73.94 83.59,73.86 83.71,73.86 83.79,73.94 83.79,74.61 83.87,74.69 84.04,74.69 84.12,74.77 84.12,74.88 84.04,74.96 82.57,74.96 82.49,75.04 82.49,75.16 82.57,75.24 84.04,75.24 84.12,75.32 84.12,75.43 84.04,75.51 82.57,75.51 82.49,75.59 82.49,75.7 82.57,75.78 84.04,75.78 84.12,75.86 84.12,75.98 84.04,76.06 82.57,76.06 82.49,76.14 82.49,76.25 82.57,76.33 84.04,76.33 84.12,76.41 84.12,76.53 84.04,76.61 82.57,76.61 82.49,76.69 82.49,76.8 82.57,76.88 84.04,76.88 84.12,76.96 84.12,77.08 84.04,77.16 82.57,77.16 82.49,77.24 82.49,77.35 82.57,77.43 83.34,77.43 83.42,77.51 83.42,77.62 83.34,77.7 82.57,77.7 82.49,77.79 82.49,79.38 82.74,79.64 83.62,79.64 83.76,79.49 83.76,79.3 83.61,79.15 83,79.15 82.79,78.94 82.79,78.37 83.04,78.12 83.81,78.12 84.31,78.62 85.07,78.62 85.25,78.44 85.25,78.14 84.69,77.57 v1(83.83,77.57)
  BOTTOM w0.147: U35.36 85.67,71.66 v1(84.58,72.76) ; v1(83.83,77.57) 84.46,77.57 84.73,77.84 R488.2
ICSSM_MII0/MII1_RXDV_ADD: length 35.4
  TOP w0.147: v1(76.89,97.04) 76.24,97.04 75.84,96.64 J8.45 ; R529.2 v1(75.44,69.67)
  BOTTOM w0.147: v1(76.89,97.04) 77.5,96.43 77.5,94.68 77.79,94.39 78.38,94.39 78.89,93.88 78.89,92.88 76.5,90.49 76.5,84.56 78.24,82.83 78.24,79.95 74.87,76.58 74.87,70.23 v1(75.44,69.67) R529.2
ICSSM_MII0/MII1_RXDV_ON: length 66.7
  TOP w0.147: R242.1 85.23,74.41 v1(84.58,74.41) R230.1 ; R481.2 v1(99.85,94.93)
  L08_SIG2 w0.091: v1(99.85,94.93) 100.21,95.3 100.21,98.3 100.07,98.44 99.47,98.44 99.3,98.27 99.3,91.32 99.56,91.06 99.56,88.83 98.24,87.51 98.24,87.22 98.35,87.11 99.2,87.11 99.31,87 99.31,86.85 99.21,86.74 98.35,86.74 98.24,86.64 98.24,86.48 98.35,86.38 99.2,86.38 99.31,86.27 99.31,86.11 99.21,86.01 98.35,86.01 98.24,85.9 98.24,84.68 98.35,84.57 99.24,84.57 99.35,84.46 99.35,84.31 99.24,84.2 98.35,84.2 98.24,84.1 98.24,83.59 97.75,83.1 97.75,82.95 98.03,82.67 98.03,82.52 97.92,82.41 97.77,82.41 97.49,82.69 97.34,82.69 97.23,82.58 97.23,82.43 97.51,82.15 97.51,82 97.4,81.9 97.25,81.9 96.97,82.17 96.82,82.17 96.72,82.07 96.72,81.91 96.99,81.64 96.99,81.49 96.89,81.38 96.73,81.38 96.46,81.66 96.31,81.66 95.26,80.61 90.35,80.61 87.24,77.5 87.24,75.97 85.73,74.46 85.73,68.97 85.47,68.71 85.14,68.71 84.51,69.34 84.15,69.34 83.96,69.53 83.96,70.07 84.21,70.33 84.95,70.33 85.18,70.57 85.18,74.18 84.95,74.41 v1(84.58,74.41)
  BOTTOM w0.147: v1(84.58,74.41) 85.3,74.41 86.92,72.79 U35.38 ; R481.2 v1(99.85,94.93)
ICSSM_MII0/MII1_RXER_ADD: length 35.3
  TOP w0.147: R530.2 v1(75.44,68.68) ; J8.39 76.2,95.44 v1(76.89,96.13)
  BOTTOM w0.147: v1(76.89,96.13) 76.89,95.83 77.09,95.63 77.09,94.49 77.6,93.98 78.01,93.98 78.43,93.55 78.43,92.83 76.15,90.55 76.15,84.49 77.91,82.73 77.91,80.04 74.58,76.71 74.58,69.54 v1(75.44,68.68) R530.2
ICSSM_MII0/MII1_RXER_ON: length 64.8
  TOP w0.147: v1(99.85,93.94) R482.2 99.07,93.61 98.9,93.44 97.34,93.44 97.16,93.25 97.16,91.78 97.86,91.08 98.22,91.08 98.66,90.64 98.66,89.94 98.29,89.56 97.87,89.56 96.74,88.43 96.74,85.19 91.15,79.59 v1(91.15,77.36)
  L08_SIG2 w0.091: v1(91.15,77.36) 94.21,74.3 95.56,74.3 96.31,73.54 96.31,63.04 98.16,61.19 99.82,61.19 102.42,58.59 109.03,58.59 109.32,58.88 111.03,58.88 v1(113.02,56.88)
  BOTTOM w0.147: R223.1 v1(113.02,56.88) ; v1(91.15,77.36) 91.47,77.04 R228.2 R240.1 91.31,75.36 R213.2 ; R482.2 v1(99.85,93.94)
ICSSM_MII0/MII1_RXLINK_ADD: length 35.3
  TOP w0.147: v1(75.98,96.13) 75.86,96.24 J8.43 ; R532.2 v1(75.44,66.7)
  BOTTOM w0.147: R532.2 v1(75.44,66.7) 73.99,68.14 73.99,76.95 77.26,80.22 77.26,82.55 75.42,84.4 75.42,92.81 76.58,93.97 76.58,95.1 75.98,95.7 v1(75.98,96.13)
ICSSM_MII0/MII1_RXLINK_ON: length 66.7
  TOP w0.147: v1(99.89,91.96) R484.2 99.07,91.1 99.6,90.58 99.6,88.79 99.07,88.27 99.07,87.03 97.43,85.38 97.43,84.16 94.58,81.31 94.58,79.5 96.97,77.11 96.97,74.44 96.33,73.79 v1(95.1,73.79) ; R222.1 v1(113,54.19)
  L08_SIG2 w0.091: v1(113,54.19) 111.34,55.85 108.78,55.85 107.75,54.81 98.06,54.81 95.96,56.91 95.96,65.72 95.1,66.57 v1(95.1,73.79)
  BOTTOM w0.147: U35.47 91.42,72.68 92.54,73.79 R239.1 R227.2 v1(95.1,73.79) ; R484.2 v1(99.89,91.96)
ICSSM_MII0/MII1_TXCLK_ADD: length 18.5
  TOP w0.147: R512.2 68.45,84.78 v1(69.08,85.41) 68.26,86.23 68.26,88.5 68.43,88.67 68.67,88.67 68.82,88.52 68.82,86.99 69.8,86.01 75.32,86.01 75.72,86.41 75.72,88.06 75.54,88.24 J8.3
  BOTTOM w0.147: v1(69.08,85.41) 69.08,84.77 68.45,84.13 R512.2
ICSSM_MII0/MII1_TXCLK_ON: length 54.4
  TOP w0.147: R496.2 v1(99.76,98.91)
  L08_SIG2 w0.091: v1(99.76,98.91) 101.35,98.91 101.83,98.42 101.83,88.75 100.56,87.48 100.56,84.36 96.4,80.2 90.5,80.2 88.55,78.25 88.55,76.37 87.89,75.71 87.89,75.01 86.29,73.4 86.29,68.35 84.78,66.84 84.38,66.84 83.36,67.86 83.36,69.88 83.17,70.06 82.85,70.06 82.69,69.91 v1(82.69,66.92)
  BOTTOM w0.147: R210.1 v1(82.69,66.92) ; R496.2 v1(99.76,98.91)
ICSSM_MII0/MII1_TXD0_ADD: length 17.9
  TOP w0.147: J8.7 75.67,89.04 76.02,88.7 76.02,83.78 77.24,82.56 77.24,80.18 75.04,77.98 75.04,75.19 v1(75.58,74.65) R513.2
  BOTTOM w0.147: v1(75.58,74.65) R513.2
ICSSM_MII0/MII1_TXD0_ON: length 56.8
  TOP w0.147: R497.2 v1(100.52,103.03)
  L08_SIG2 w0.091: v1(100.52,103.03) 100.97,103.03 102.12,101.87 102.12,88.54 100.85,87.28 100.85,86.17 101.58,85.44 101.58,84.95 95.92,79.29 94.24,79.29 93.88,79.65 90.22,79.65 88.81,78.24 88.81,76.23 88.14,75.56 88.14,74.77 86.56,73.19 86.56,68.19 v1(83.26,64.88)
  BOTTOM w0.147: R497.2 v1(100.52,103.03) ; v1(83.26,64.88) 83.58,65.21 83.9,65.21 84.2,65.5 84.2,66.3 85.24,67.34 U35.28
ICSSM_MII0/MII1_TXD1_ADD: length 17.7
  TOP w0.147: R514.2 v1(75.58,75.68) 75.35,75.91 75.35,76.2 75.68,76.53 75.68,76.81 75.35,77.13 75.35,77.79 77.59,80.03 77.59,82.71 76.31,83.99 76.31,88.87 75.74,89.44 J8.9
  BOTTOM w0.147: R514.2 v1(75.58,75.68)
ICSSM_MII0/MII1_TXD1_ON: length 57.1
  TOP w0.147: R498.2 v1(100.52,104.02)
  L08_SIG2 w0.091: v1(100.52,104.02) 102.4,102.15 102.4,88.49 101.13,87.22 101.13,86.28 101.86,85.55 101.86,84.84 96.02,79 94.14,79 93.77,79.37 90.22,79.37 89.08,78.24 89.08,76.1 88.43,75.45 88.43,74.59 86.87,73.04 86.87,67.47 v1(84.02,64.63)
  BOTTOM w0.147: U35.27 85.15,66.84 84.58,66.27 84.58,65.18 v1(84.02,64.63) ; R498.2 v1(100.52,104.02)
ICSSM_MII0/MII1_TXD2_ADD: length 17.7
  TOP w0.147: R515.2 v1(76.21,77.22) 75.89,77.22 75.76,77.35 75.76,77.71 77.94,79.89 77.94,82.85 76.61,84.19 76.61,90.14 76.46,90.29 76.13,90.29 75.69,89.84 J8.11
  BOTTOM w0.147: R523.2 76.21,77.22 v1(76.21,77.22)
ICSSM_MII0/MII1_TXD2_ON: length 57.2
  TOP w0.147: R499.2 v1(100.52,105.01)
  L08_SIG2 w0.091: v1(100.52,105.01) 102.69,102.84 102.69,88.43 101.42,87.17 101.42,86.4 102.15,85.67 102.15,84.71 96.14,78.71 94.02,78.71 93.64,79.08 90.2,79.08 89.37,78.25 89.37,76.01 88.74,75.39 88.74,74.46 87.18,72.91 87.18,67.03 v1(84.8,64.64)
  BOTTOM w0.147: v1(84.8,64.64) 84.86,64.7 84.86,65.08 84.91,65.14 84.91,66.07 85.18,66.34 U35.26 ; R499.2 v1(100.52,105.01)
ICSSM_MII0/MII1_TXD3_ADD: length 18
  TOP w0.147: R516.2 76.95,78.02 77.44,78.51 v1(77.46,78.51) 77.46,78.74 77.63,78.91 78.13,78.91 78.29,79.07 78.29,83 76.9,84.39 76.9,90.74 76.58,91.06 76.18,91.06 75.83,90.71 75.83,90.48 75.59,90.24 J8.13
  BOTTOM w0.147: R516.2 76.95,78.18 77.27,78.51 v1(77.46,78.51)
ICSSM_MII0/MII1_TXD3_ON: length 57
  TOP w0.147: R500.2 v1(100.52,106)
  L08_SIG2 w0.091: v1(85.67,64.63) 87.46,66.42 87.46,72.81 89.05,74.4 89.05,75.32 89.6,75.88 89.6,78.21 90.19,78.8 93.53,78.8 93.9,78.43 96.26,78.43 102.43,84.6 102.43,85.79 101.7,86.52 101.7,87.05 102.96,88.32 102.96,103.56 v1(100.52,106)
  BOTTOM w0.147: v1(85.67,64.63) U35.25 ; R500.2 v1(100.52,106)
ICSSM_MII0/MII1_TXEN_ADD: length 18.2
  TOP w0.147: v1(75.98,94.79) 75.83,94.64 J8.35 ; R511.2 69.44,84.52 v1(69.77,84.86)
  BOTTOM w0.147: R511.2 69.44,84.52 v1(69.77,84.86) 69.77,86.9 70.29,87.42 70.91,87.42 71.52,88.03 71.52,89.18 71,89.7 71,93.63 71.94,94.57 75.75,94.57 v1(75.98,94.79)
ICSSM_MII0/MII1_TXEN_ON: length 57.3
  TOP w0.147: R495.2 v1(99.76,99.9)
  L08_SIG2 w0.091: v1(84.58,73.52) 84.08,73.03 84.08,70.76 84,70.67 83.71,70.67 83.54,70.84 83.54,74.1 84.3,74.87 85.79,74.87 87.03,76.11 87.03,77.59 90.27,80.83 94.19,80.83 95.11,81.75 96.02,81.75 97.96,83.69 97.96,88.02 98.64,88.7 98.64,89.35 98.95,89.66 98.95,94.81 98.07,95.69 98.07,95.89 98.17,96 98.89,96 98.99,96.1 98.99,96.26 98.89,96.36 98.17,96.36 98.07,96.47 98.07,96.62 98.17,96.73 98.89,96.73 98.99,96.84 98.99,96.99 98.89,97.09 98.17,97.09 98.07,97.2 98.07,97.35 98.17,97.46 98.89,97.46 98.99,97.57 98.99,97.72 98.89,97.83 98.17,97.83 98.07,97.93 98.07,98.08 98.17,98.19 98.89,98.19 98.99,98.3 98.99,98.45 98.89,98.56 98.17,98.56 98.07,98.66 98.07,98.82 98.17,98.92 98.88,98.92 98.98,99.03 98.98,99.18 98.87,99.29 98.17,99.29 98.07,99.4 98.07,99.84 98.52,100.3 99.36,100.3 v1(99.76,99.9)
  BOTTOM w0.147: v1(84.58,73.52) 85.26,73.52 86.42,72.36 U35.37 ; R495.2 v1(99.76,99.9)
ICSSM_MII0_COL: length 15.2
  TOP w0.147: v1(65.26,62.89) 65.73,62.42 66.73,62.42 67.44,63.13 70,63.13 70.76,63.89 70.76,65.07 71.09,65.4 72.38,65.4 72.93,64.85 72.93,63.86 73.9,62.89 U87.25
  BOTTOM w0.147: v1(65.26,62.89) 65.76,62.39 U82.13
ICSSM_MII0_COL_ADD: length 27.1
  BOTTOM w0.147: U82.24 72.35,63.39 72.81,63.85 72.81,64.52 70.57,66.76 68.68,66.76 67.48,67.96 67.48,76.37 68.5,77.39 68.5,77.83 70.3,79.64 70.3,81.35 70.96,82.01 70.96,83 71.41,83.45 R517.1
ICSSM_MII0_COL_ON: length 52.3
  TOP w0.147: R493.1 v1(97.55,96.93)
  L08_SIG2 w0.091: v1(97.55,96.93) 97.55,96.55 97.17,96.17 97.17,90.07 96.6,89.5 96.6,88.6 95.79,87.79 95.79,84.43 94.62,83.26 94.62,82.86 93.59,81.84 89.89,81.84 85.66,77.61 85.07,77.61 82.25,74.79 82.25,72.16 80.51,70.42 80.51,66.61 79.01,65.11 74.38,65.11 v1(72.17,62.89)
  BOTTOM w0.147: v1(72.17,62.89) U82.25
ICSSM_MII0_CRS: length 14.4
  TOP w0.147: U87.23 74.09,63.89 73.65,64.33 73.65,66.33 73.16,66.82 71.49,66.82 70.41,65.74 70.41,64.11 69.76,63.46 67.26,63.46 66.69,62.89 v1(66.18,62.89)
  BOTTOM w0.147: U82.14 v1(66.18,62.89)
ICSSM_MII0_CRS_ADD: length 23.6
  BOTTOM w0.147: U82.22 71.1,64.39 71.21,64.5 71.21,65.18 70.07,66.31 68.7,66.31 67.18,67.84 67.18,76.49 68.16,77.47 68.16,77.97 69.97,79.77 69.97,83 70.42,83.45 R518.1
ICSSM_MII0_CRS_ON: length 52.6
  TOP w0.147: R494.1 v1(97.55,97.92)
  L08_SIG2 w0.091: v1(97.55,97.92) 97.08,97.45 97.08,96.58 96.95,96.45 96.95,90.18 96.28,89.52 96.28,88.66 95.5,87.88 95.5,84.54 94.36,83.4 94.36,82.98 93.41,82.03 89.81,82.03 85.58,77.8 84.99,77.8 81.99,74.81 81.99,72.24 80.24,70.48 80.24,66.73 78.89,65.38 73.66,65.38 v1(72.17,63.89)
  BOTTOM w0.147: v1(72.17,63.89) U82.23
ICSSM_MII0_RXCLK: length 16.7
  TOP w0.147: v1(65.26,61.89) 65.08,61.71 65.08,61.38 65.29,61.17 66.51,61.17 66.69,60.99 66.69,60.2 66.83,60.06 67.15,60.06 67.33,60.24 67.33,60.81 67.6,61.08 70.01,61.08 70.14,61.21 70.14,61.83 70.27,61.96 70.45,61.96 70.58,61.83 70.58,61.21 70.71,61.08 70.92,61.08 71.06,60.94 71.51,60.94 71.92,61.35 72.47,61.35 72.62,61.2 72.62,60.55 72.8,60.37 73.04,60.37 73.57,60.89 U87.29
  BOTTOM w0.147: v1(65.26,61.89) 65.76,61.39 U82.11
ICSSM_MII0_RXCLK_ADD: length 27.4
  L08_SIG2 w0.091: v1(71.25,61.39) 71.71,61.85 71.71,64.45 70.01,66.15 70.01,69.78 70.32,70.09 70.74,70.09 72.13,68.7 74.2,68.7 74.77,68.14 74.77,67.92 74.63,67.79 73.87,67.79 73.73,67.65 73.73,67.46 73.87,67.33 74.63,67.33 74.77,67.2 74.77,66.31 75.11,65.97 76.05,65.97 76.33,66.25 76.33,67.71 76.88,68.26 77.76,68.26 78.33,67.69 v1(78.54,67.69)
  BOTTOM w0.147: U82.28 v1(71.25,61.39) ; v1(78.54,67.69) 78.16,67.22 77.33,67.22 76.88,67.68 R539.1
ICSSM_MII0_RXCLK_ON: length 57.8
  TOP w0.147: R483.1 v1(97.63,92.95)
  L08_SIG2 w0.091: v1(97.63,92.95) 98.11,92.47 98.11,90.3 97.17,89.37 97.17,83.98 95.57,82.39 94.81,82.39 93.88,81.45 90.07,81.45 86.35,77.73 86.35,77.06 85.73,76.44 84.5,76.44 82.76,74.7 82.76,71.92 80.99,70.15 80.99,63.82 80.53,63.36 78.75,63.36 78.49,63.11 78.49,62.88 78.39,62.77 78.04,62.77 77.93,62.66 77.93,62.51 78.04,62.4 78.39,62.4 78.49,62.3 78.49,62.14 78.39,62.04 78.04,62.04 77.93,61.93 77.93,61.78 78.04,61.67 78.39,61.67 78.49,61.56 78.49,61.28 78.11,60.89 74.83,60.89 74.72,60.79 74.72,60.45 74.61,60.34 74.46,60.34 74.35,60.45 74.35,60.79 74.25,60.89 74.09,60.89 73.99,60.79 73.99,60.45 73.88,60.34 73.73,60.34 73.62,60.45 73.62,60.79 73.51,60.89 73.36,60.89 73.26,60.79 73.26,60.45 73.15,60.34 73,60.34 72.89,60.45 72.89,60.79 72.78,60.89 v1(72.17,60.89)
  BOTTOM w0.147: v1(72.17,60.89) U82.29
ICSSM_MII0_RXD0: length 16.9
  TOP w0.147: v1(65.26,56.42) 65.26,55.06 66.01,54.31 68.92,54.31 69.26,54.65 70.93,54.65 71.85,55.57 73.35,55.57 74.26,54.65 76.15,54.65 76.72,55.22 U87.41
  BOTTOM w0.147: v1(65.26,56.42) 65.74,56.89 U82.2
ICSSM_MII0_RXD0_ADD: length 27.5
  TOP w0.147: R533.1 76.92,73.86 76.68,74.11 75.82,74.11 v1(75.34,73.63)
  L03_SIG1 w0.091: v1(67.5,55.11) 67.17,55.43 67.17,65.13 67.46,65.42 67.65,65.42 67.77,65.31 67.96,65.31 68.09,65.44 68.09,65.63 67.98,65.75 67.98,65.94 68.11,66.07 68.3,66.07 68.41,65.96 68.6,65.96 68.74,66.09 68.74,66.28 68.62,66.39 68.62,66.58 68.76,66.72 68.95,66.72 69.06,66.6 69.25,66.6 69.38,66.74 69.38,66.93 69.27,67.04 69.27,67.23 69.4,67.36 69.59,67.36 69.71,67.25 69.9,67.25 70.03,67.38 70.03,67.57 69.92,67.69 69.92,67.88 75.34,73.3 v1(75.34,73.63)
  BOTTOM w0.147: v1(67.5,55.11) 67.82,55.11 67.96,55.25 U82.42
ICSSM_MII0_RXD0_ON: length 57.5
  TOP w0.147: v1(85.54,82.11) 84.97,82.67 84.35,82.67 83.79,82.11 R476.1
  L03_SIG1 w0.091: v1(68.46,55.11) 68.46,54.62 68.07,54.22 65.88,54.22 63.31,56.79 63.31,60.8 63.51,61 63.75,61 63.93,60.82 63.93,58.57 64.11,58.39 64.43,58.39 65.06,59.02 65.06,60.87 64.7,61.23 64.7,62.06 65.01,62.36 66.35,62.36 66.63,62.64 66.63,65.36 74.61,73.34 74.61,74.57 75.2,75.16 78.6,75.16 79.21,75.77 79.21,82.21 79.95,82.96 84.34,82.96 85.19,82.11 v1(85.54,82.11)
  BOTTOM w0.147: U82.41 v1(68.46,55.11)
ICSSM_MII0_RXD1: length 17.3
  TOP w0.147: U87.39 74.78,55.94 74.72,55.88 71.65,55.88 71.34,55.58 69.24,55.58 68.96,55.3 68.96,54.85 68.72,54.6 66.33,54.6 65.66,55.28 65.66,56.06 65.91,56.31 65.91,56.62 65.65,56.87 64.53,56.87 64.36,57.04 64.36,57.25 64.51,57.39 v1(65.26,57.39)
  BOTTOM w0.147: v1(65.26,57.39) U82.3
ICSSM_MII0_RXD1_ADD: length 27.7
  TOP w0.147: R534.1 76.94,72.66 76.53,73.07 76.52,73.07 76.49,73.1 75.8,73.1 v1(75.34,72.64)
  L03_SIG1 w0.091: v1(75.34,72.64) 70.87,68.17 70.87,67.62 67.45,64.2 67.45,56.62 68.04,56.03 69.51,56.03 v1(70.43,55.11)
  BOTTOM w0.147: U82.40 68.96,54.88 69.22,54.63 69.96,54.63 v1(70.43,55.11)
ICSSM_MII0_RXD1_ON: length 57.5
  TOP w0.147: v1(85.54,81.12) 85.03,81.62 84.29,81.62 83.79,81.12 R477.1
  L03_SIG1 w0.091: v1(69.46,55.11) 69,55.57 68.22,55.57 68.01,55.37 68.01,54.65 67.86,54.5 66.13,54.5 64.34,56.29 64.34,57.5 64.7,57.86 65.47,57.86 65.79,57.54 65.79,56.59 65.95,56.42 66.67,56.42 66.9,56.65 66.9,59.63 66.79,59.74 65.8,59.74 65.69,59.84 65.69,60 65.8,60.1 66.79,60.1 66.9,60.21 66.9,60.91 66.79,61.01 66.55,61.01 66.44,61.12 66.44,61.27 66.55,61.38 66.79,61.38 66.9,61.49 66.9,65.25 74.89,73.24 74.89,73.95 75.07,74.13 78.63,74.13 79.5,75 79.5,81.94 80.24,82.68 83.26,82.68 84.36,81.59 85.06,81.59 v1(85.54,81.12)
  BOTTOM w0.147: U82.39 v1(69.46,55.11)
ICSSM_MII0_RXD2: length 16.8
  TOP w0.147: v1(66.18,57.89) 65.85,57.57 65.85,57.16 66.46,56.55 67.15,56.55 67.32,56.71 67.32,57.09 67.52,57.3 69.83,57.3 70.02,57.1 70.02,56.52 69.87,56.37 68.61,56.37 68.46,56.23 68.46,55.73 68.59,55.6 68.85,55.6 69.18,55.93 70.67,55.93 70.86,56.11 70.86,56.54 71.16,56.84 71.55,56.84 71.99,56.39 U87.38
  BOTTOM w0.147: U82.4 v1(66.18,57.89)
ICSSM_MII0_RXD2_ADD: length 28
  TOP w0.147: v1(75.34,71.65) 75.8,72.11 76.49,72.11 76.52,72.08 76.53,72.08 76.94,71.67 R535.1
  L08_SIG2 w0.091: v1(72.17,56.89) 72.12,56.94 71.04,56.94 70,57.98 70,64.15 68.63,65.52 68.63,71.79 69.21,72.37 70.65,72.37 71.37,71.65 v1(75.34,71.65)
  BOTTOM w0.147: v1(72.17,56.89) U82.37
ICSSM_MII0_RXD2_ON: length 57.8
  TOP w0.147: v1(85.42,80.26) 85.1,80.58 84.28,80.58 R479.1
  L03_SIG1 w0.091: v1(85.42,80.26) 84.94,79.78 84.94,79.13 85.54,78.53 85.54,78.04 84.72,77.22 84.72,75.78 84.85,75.65 84.85,75.65 85.66,74.84 85.66,74.49 86.52,73.63 86.52,71.17 86.09,70.74 86.09,68.55 85.85,68.31 84.29,68.31 84.1,68.12 84.1,67.62 83.95,67.47 82.39,67.47 82.01,67.09 80.99,67.09 80,68.09 80,70.23 79.06,71.17 78.44,71.17 78.21,70.95 77.88,70.95 76.07,69.14 74.64,69.14 69.99,64.49 69.99,56.31 70.86,55.45 70.86,54.79 70.42,54.36 69.1,54.36 68.55,53.81 68.55,53.37 68.78,53.14 69.28,53.14 69.74,53.6 70.8,53.6 71.53,54.34 71.53,56.06 v1(71.32,56.27)
  BOTTOM w0.147: v1(71.32,56.27) 71.2,56.39 U82.38
ICSSM_MII0_RXD3: length 16.6
  TOP w0.147: v1(65.26,58.39) 66.76,58.39 66.92,58.23 66.92,57.95 66.28,57.32 66.28,57.15 66.46,56.97 66.74,56.97 67.42,57.65 70.17,57.65 70.32,57.51 70.32,56.94 70.46,56.79 70.67,56.79 70.79,56.91 70.79,57.75 70.94,57.9 71.48,57.9 71.99,57.39 72.64,57.39 72.77,57.26 72.77,56.83 72.9,56.7 73.08,56.7 73.21,56.83 73.21,57.26 73.34,57.39 U87.36
  BOTTOM w0.147: v1(65.26,58.39) U82.5
